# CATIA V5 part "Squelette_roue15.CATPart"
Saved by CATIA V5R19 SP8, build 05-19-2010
Part number: Squelette_roue15
Bounding box of the stored display mesh (mm): x -20 to 10, y -20 to -20, z -10 to 10
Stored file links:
  G:\EU_thinkMotion\CFAO_2010\MMS_groupe2\MMS_groupe2\A reprendre\jcauchy\Squelette_roue15.CATPart
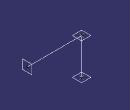
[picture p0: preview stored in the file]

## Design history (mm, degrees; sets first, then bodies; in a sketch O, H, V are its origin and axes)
Parameters
  Longueurfixation_roue15 = 20 mm
  Rayonroue_roue15 = 30 mm
Set1
  Point1: (-20, -20, 10 {= Longueurfixation_roue15 -10mm})
  Point2: (-20, -20, -10)
  Line1: type PtPt, FirstPoint Point2, SecondPoint Point1
  Point3: type OnCurve, Support Line1, Length 20
  Line2: type Angle, RefPoint Point3, Curve Line1, Support zx-plane, Start 0, End 30 {= Rayonroue_roue15}, Angle 90
  Plane1: type Normal, Curve Line2, RefPoint vertex of Line2
  Plane2: type Normal, Curve Line1, RefPoint Point1
  Plane3: type Normal, Curve Line1, RefPoint Point2
Body1 (main body)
